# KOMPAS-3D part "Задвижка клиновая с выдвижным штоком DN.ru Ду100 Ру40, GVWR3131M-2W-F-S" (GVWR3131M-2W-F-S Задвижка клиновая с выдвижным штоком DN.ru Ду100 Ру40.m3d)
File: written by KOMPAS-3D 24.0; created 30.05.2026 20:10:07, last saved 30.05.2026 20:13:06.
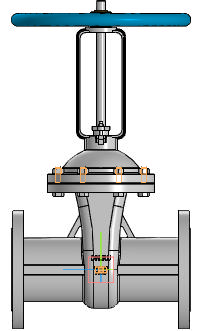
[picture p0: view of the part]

Document properties: Автор: R2D2; Полное имя файла: E:\Работа\Зайцев\GVWR3131M-2W-F-S Задвижка клиновая с выдвижным штоком DN.ru Ду50-100 Ру40\исходные материалы\DN100\GVWR3131M-2W-F-S Задвижка клиновая с выдвижным штоком DN.ru Ду100 Ру40.m3d

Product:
- Component [detail]: Деталь2  | qty 1  | pos. 1  | Масса: 5.406695; Автор: R2D2; additional columns: Типовые; source file: Деталь2 Деталь2.m3d
- Component [detail]: ANSI B18.2.4.2M - M5x0,8 - 8  | designation ANSI B18.2.4.2M - M5x0,8  | qty 2  | pos. 2  | Комментарий: Типы метрических   шестигранных гаек   2; Автор: R2D2; additional columns: Сталь, мягкая; source file: ANSI B18.2.4.2M - M5x0,8 ANSI B18.2.4.2M - M5x0,8 - 8.m3d
- Component [detail]: Деталь1  | qty 1  | pos. 3  | additional columns: Типовые; source file: 2.m3d
- Component [detail]: Деталь1  | qty 1  | pos. 3  | Автор: R2D2; additional columns: Типовые; source file: 3.m3d
- Component [detail]: Деталь1  | qty 2  | pos. 3  | Автор: R2D2; additional columns: Типовые; source file: 1.m3d
- Component [standard]: Болт М12-6gx50.88.45Г.019 ГОСТ 7798-70  | qty 8  | Материал: Сталь 45Г (density 7850 kg/m3); Масса: 0.06053; Раздел спецификации: Стандартные изделия; Рассекать на разрезах: no; additional columns: BOSimple***Material:39848d99-529e-4aa2-825c-393daa009d15
- Component [standard]: Гайка М12-6H ГОСТ 5915-70  | qty 24  | Масса: 0.0184; Раздел спецификации: Стандартные изделия; Рассекать на разрезах: no
- Part/product: Задвижка клиновая с выдвижным штоком DN.ru Ду100 Ру40  | designation GVWR3131M-2W-F-S
    Масса: 39
    Раздел спецификации: Прочие изделия
    Примечание: D040-09952

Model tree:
1. Массив по концентрической сетке:1  (labels: Грань.Твердое тело1)  (8 pattern instances)
     Шаг 2 = 360
2. Массив по концентрической сетке:2  (labels: Грань.Твердое тело1)  (2 pattern instances)
     Шаг 2 = 360
3. Эскиз:1
4. Элемент выдавливания:1  (labels: Грань.Твердое тело1)
     Расстояние 1 = 76; Смещение 1 = 1
5. Элемент выдавливания:2  (with: Грань.Элемент выдавливания:1, Грань.Элемент вращения:1)
     Расстояние 1 = 65.7931
6. Элемент выдавливания:3  (with: Грань.Элемент выдавливания:1, Грань.Элемент вращения:1)
     Расстояние 1 = 71.5338
7. Элемент выдавливания:4  (with: Грань.Элемент выдавливания:1, Грань.Элемент вращения:1)  (labels: Грань.Твердое тело1; Грань.Solid1; Solid1; Твердое тело1)
     Расстояние 1 = 88.75; Расстояние = -525; Расстояние = -175; Ориентация = 2

Referenced files in E:\Работа\Зайцев\GVWR3131M-2W-F-S Задвижка клиновая с выдвижным штоком DN.ru Ду50-100 Ру40\исходные материалы\DN100\: Деталь2 Деталь2.m3d, ANSI B18.2.4.2M - M5x0,8 ANSI B18.2.4.2M - M5x0,8 - 8.m3d, 2.m3d, 3.m3d, 1.m3d
Referenced files in C:\Program Files\ASCON\KOMPAS-3D v24\Libs\PolynomLib\DATA\vault\Methods\Kompas\3D\: PLib_Bolt_1_900.m3d, PLib_Nut_OST92_900.m3d
Referenced files in E:\Работа\Зайцев\GVWR3131M-2W-F-S Задвижка клиновая с выдвижным штоком DN.ru Ду50-200 Ру63\DN100\исходные материалы\: 1.m3d, ANSI B18.2.4.2M - M5x0,8 ANSI B18.2.4.2M - M5x0,8 - 8.m3d
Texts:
  BOSimple***PART:25ccc031-f2ed-a43b-e633-090566d53ffa***SHORTLOC:Root±30±20±10±80±10±©{}30±©{BASE}130±290[9;Цинковое, хроматированное;Сталь 45Г ГОСТ 4543-2016;50;12;19;1,75;8.8]
  BOSimple***Material:39848d99-529e-4aa2-825c-393daa009d15
  BOSimple***PART:dfaf85ed-3e43-003f-b29c-9c5b054070d3***SHORTLOC:Root±30±10±20±©{}110±10±50±60[Нет;Без покрытия;Без указания материала;-;12;1,75;19]
  GVWR3131M-2W-F-S
  DN100
  GOST 26.020 Pr3
  PN40
  ANSI B18.2.4.2M - M5x0,8 ANSI B18.2.4.2M - M5x0,8 - 8 (1)
  Деталь1 Деталь1
  Деталь1 Деталь1 (1)
  Деталь1 Деталь1 (2)
  Болт М12-6gx50.88.45Г.019 ГОСТ 7798-70 (1)
  hole1
  hole2
  Гайка М12-6H ГОСТ 5915-70 (1)
  bcut1
  hcut1
  cut1
  Гайка М12-6H ГОСТ 5915-70 (2)
  Гайка М12-6H ГОСТ 5915-70 (3)
  Ось Z.Начало координат
  Ось Y.Начало координат
  Плоскость ZX.Начало координат
  Плоскость XY.Начало координат
  Plane. Начало координат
